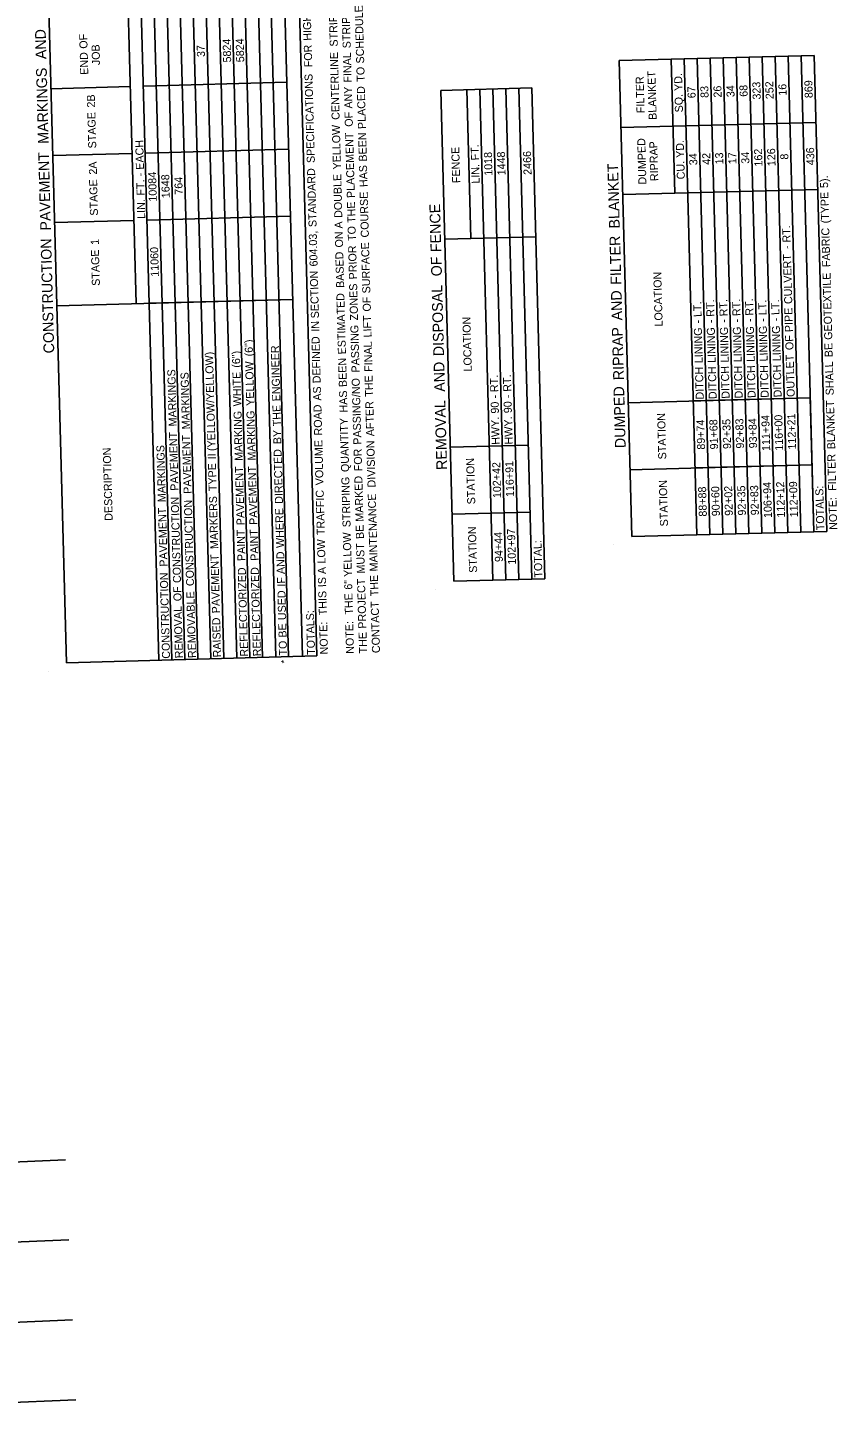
# Model space of a CAD drawing. Extents: x 1930091 to 1931962, y 596452 to 607874.
# Drawn here: x 1930751 to 1931358, y 596452 to 597489 of the extents above; entities that cross this region are included whole.
import ezdxf

# ---------------------------------------------------------------- set-up
doc = ezdxf.new("R2010")
doc.units = 0
for name, color, linetype in [('BR_Pr_Bent_CL', 7, 'Continuous'), ('Default', 7, 'Continuous'), ('R_Border', 7, 'Continuous')]:
    doc.layers.add(name, color=color, linetype=linetype)

msp = doc.modelspace()

# ---------------------------------------------------------------- linework, layer by layer
at = {"layer": 'BR_Pr_Bent_CL'}
for p, q in [((1930779.3, 596640.3), (1930579.5, 596631.6)), ((1930781.9, 596580.4), (1930582.1, 596571.7)), ((1930784.5, 596520.4), (1930584.7, 596511.8)), ((1930787.1, 596460.5), (1930587.3, 596451.8))]:
    msp.add_line(p, q, dxfattribs=at)
at = {"layer": 'Default'}
for p, q in [((1930832.2, 597282.1), (1930815, 597924.9)), ((1930849.2, 597014.8), (1930824.7, 597925.1)), ((1930858.9, 597015.1), (1930834.5, 597925.4)), ((1930868.7, 597015.3), (1930844.2, 597925.6)), ((1930878.4, 597015.6), (1930854, 597925.9)), ((1930888.2, 597015.8), (1930863.7, 597926.2)), ((1930897.9, 597016.1), (1930873.5, 597926.4)), ((1930907.7, 597016.4), (1930883.2, 597926.7)), ((1930917.4, 597016.6), (1930893, 597926.9)), ((1930927.1, 597016.9), (1930902.7, 597927.2)), ((1930936.9, 597017.1), (1930912.5, 597927.5)), ((1930946.6, 597017.4), (1930922.2, 597927.7)), ((1930956.9, 597017.7), (1930932.4, 597928)), ((1930967.6, 597018), (1930943.2, 597928.3)), ((1930780, 597012.9), (1930755.5, 597923.3)), ((1931340.5, 597468.1), (1931194.3, 597464.2)), ((1931311.1, 597110.3), (1931301.5, 597467.1)), ((1931320.8, 597110.6), (1931311.3, 597467.3)), ((1931330.6, 597110.9), (1931321, 597467.6)), ((1931340.3, 597111.1), (1931330.7, 597467.8)), ((1931350.1, 597111.4), (1931340.5, 597468.1)), ((1931203.9, 597107.5), (1931194.3, 597464.2)), ((1931236, 597364.8), (1931233.3, 597465.2)), ((1931252.6, 597108.8), (1931243, 597465.5)), ((1931262.4, 597109), (1931252.8, 597465.7)), ((1931272.1, 597109.3), (1931262.5, 597466)), ((1931281.8, 597109.5), (1931272.3, 597466.3)), ((1931291.6, 597109.8), (1931282, 597466.5)), ((1931301.3, 597110.1), (1931291.8, 597466.8)), ((1930945.3, 597448), (1930837.6, 597445.1)), ((1930945.3, 597448), (1930837.6, 597445.1)), ((1930827.9, 597444.8), (1930768.4, 597443.2)), ((1931128.8, 597443.8), (1931060.6, 597441.9)), ((1931128.8, 597443.8), (1931060.6, 597441.9)), ((1931070.5, 597074), (1931060.6, 597441.9)), ((1931083.1, 597330.9), (1931080.1, 597442.5)), ((1931099.7, 597074.8), (1931089.8, 597442.7)), ((1931109.4, 597075), (1931099.6, 597443)), ((1931119.2, 597075.3), (1931109.3, 597443.2)), ((1931128.9, 597075.6), (1931119.1, 597443.5)), ((1931138.7, 597075.8), (1931128.8, 597443.8)), ((1931341.8, 597417.9), (1931195.6, 597414)), ((1930829.2, 597394.6), (1930769.8, 597393)), ((1930946.7, 597397.8), (1930839, 597394.9)), ((1930946.7, 597397.8), (1930839, 597394.9)), ((1931343.2, 597367.7), (1931197, 597363.8)), ((1931343.2, 597367.7), (1931245.7, 597365.1)), ((1930830.6, 597344.5), (1930771.1, 597342.9)), ((1930948, 597347.6), (1930840.3, 597344.7)), ((1930948, 597347.6), (1930840.3, 597344.7)), ((1931131.8, 597332.2), (1931063.6, 597330.3)), ((1931131.8, 597332.2), (1931092.8, 597331.1)), ((1930949.7, 597285.2), (1930772.8, 597280.5)), ((1930949.7, 597285.2), (1930842, 597282.3)), ((1931337.6, 597211.5), (1931201.2, 597207.8)), ((1931337.6, 597211.5), (1931249.9, 597209.1)), ((1931340.3, 597111.1), (1931337.6, 597211.5)), ((1931126.2, 597176), (1931067.8, 597174.4)), ((1931126.2, 597176), (1931097, 597175.2)), ((1931339, 597161.3), (1931202.5, 597157.6)), ((1931339, 597161.3), (1931251.3, 597159)), ((1931127.6, 597125.8), (1931069.1, 597124.2)), ((1931127.6, 597125.8), (1931098.3, 597125)), ((1931350.1, 597111.4), (1931203.9, 597107.5)), ((1931350.1, 597111.4), (1931203.9, 597107.5)), ((1931138.7, 597075.8), (1931070.5, 597074)), ((1931138.7, 597075.8), (1931070.5, 597074)), ((1930967.6, 597018), (1930780, 597012.9)), ((1930967.6, 597018), (1930780, 597012.9))]:
    msp.add_line(p, q, dxfattribs=at)
at = {"layer": 'R_Border'}
for p, q in [((1931190.4, 597101.2), (1931190.4, 597101.2)), ((1931057, 597067.8), (1931057, 597067.8)), ((1930766.5, 597006.7), (1930766.5, 597006.7))]:
    msp.add_line(p, q, dxfattribs=at)

# ---------------------------------------------------------------- texts
at = {"layer": 'Default'}
for s, height, p in [(' HIGHWAY', 6, (1930963.8, 597477)), (' STRIPING.', 6, (1930993.2, 597471.3)), (' STRIPE', 6, (1930983.5, 597472.6)), (' SCHEDULE', 6, (1931003.3, 597459.9)), (' AND', 8, (1930765.1, 597462.4)), (' OF', 6, (1930795.9, 597471)), ('5824', 6, (1930903.5, 597462.9)), ('5824', 6, (1930913.3, 597463.1)), ('END', 6, (1930796.4, 597453.7)), ('JOB', 6, (1930805.2, 597460.9)), ('37', 6, (1930883.9, 597467)), (' FOR', 6, (1930964.4, 597457.1)), (' CENTERLINE', 6, (1930984.9, 597417.7)), (' FINAL', 6, (1930993.9, 597445.6)), (' MARKINGS', 8, (1930766.8, 597399)), (' TO', 6, (1931003.7, 597446.3)), (' SPECIFICATIONS', 6, (1930966.3, 597385.3)), ('FILTER', 6, (1931213.4, 597424.9)), ('BLANKET', 6, (1931222.5, 597419.9)), (' YD.', 6, (1931241.9, 597439.4)), ('323', 6, (1931300.5, 597435.1)), ('252', 6, (1931310.2, 597435.4)), ('16', 6, (1931319.9, 597438)), ('869', 6, (1931339.5, 597436.2)), (' 2B', 6, (1930801.6, 597426.9)), (' ANY', 6, (1930994.5, 597426.1)), (' PLACED', 6, (1931004.6, 597410.8)), ('SQ.', 6, (1931242.2, 597425.5)), ('67', 6, (1931251.7, 597436.1)), ('83', 6, (1931261.4, 597436.4)), ('26', 6, (1931271.2, 597436.6)), ('34', 6, (1931280.9, 597436.9)), ('68', 6, (1931290.7, 597437.2)), ('STAGE', 6, (1930802.4, 597398.5)), (' YELLOW', 6, (1930985.9, 597380.5)), (' OF', 6, (1930994.8, 597412.5)), (' PLACEMENT', 6, (1930996.3, 597359.1)), (' BEEN', 6, (1931005.3, 597386.4)), ('DUMPED', 6, (1931214.8, 597371.4)), (' PAVEMENT', 8, (1930768.5, 597334)), (' EACH', 6, (1930838.2, 597380.3)), ('FENCE', 6, (1931075.2, 597372.5)), (' FT.', 6, (1931089.4, 597387.3)), ('1018', 6, (1931099.4, 597378)), ('1448', 6, (1931109.2, 597378.3)), ('2466', 6, (1931128.7, 597378.7)), ('RIPRAP', 6, (1931223.7, 597374)), (' YD.', 6, (1931243.2, 597389.2)), ('34', 6, (1931253, 597385.9)), ('42', 6, (1931262.8, 597386.2)), ('13', 6, (1931272.5, 597386.5)), ('17', 6, (1931282.3, 597386.7)), ('34', 6, (1931292, 597387)), ('162', 6, (1931301.8, 597384.9)), ('126', 6, (1931311.6, 597385.2)), ('436', 6, (1931340.8, 597385.9)), (' 2A', 6, (1930803, 597376.6)), (' HAS', 6, (1931005.8, 597367.3)), ('LIN.', 6, (1931089.8, 597372.1)), (' BLANKET', 8, (1931194.9, 597335.5)), ('CU.', 6, (1931243.6, 597375.3)), ('8', 6, (1931321.2, 597390.1)), ('STAGE', 6, (1930803.7, 597348.1)), (' FT.', 6, (1930838.7, 597360.9)), (' -', 6, (1930838.3, 597375.2)), ('10084', 6, (1930847.8, 597358.6)), ('1648', 6, (1930857.5, 597361.2)), ('764', 6, (1930867.2, 597363.8)), (' STANDARD', 6, (1930967.6, 597337.3)), (' DOUBLE', 6, (1930986.9, 597344.2)), (' 5).', 6, (1931351.1, 597366.6)), (' COURSE', 6, (1931006.8, 597329.5)), (' (TYPE', 6, (1931351.8, 597340.1)), ('LIN.', 6, (1930839.1, 597345.7)), (' THE', 6, (1930996.8, 597340.4)), (' FENCE', 8, (1931061.1, 597317.8)), (' A', 6, (1930987.1, 597336.2)), (' 604.03,', 6, (1930968.4, 597307.8)), (' ON', 6, (1930987.5, 597322)), (' TO', 6, (1930997.1, 597326.9)), (' FILTER', 8, (1931196.1, 597293.3)), (' RT.', 6, (1931322.9, 597325.7)), (' FABRIC', 6, (1931352.7, 597307.3)), ('CONSTRUCTION', 8, (1930770.9, 597244.9)), (' 1', 6, (1930804.4, 597324)), ('STAGE', 6, (1930805.1, 597295.5)), ('11060', 6, (1930849.3, 597302.3)), (' PRIOR', 6, (1930997.9, 597298.1)), (' SURFACE', 6, (1931007.9, 597287.6)), (' -', 6, (1931323.1, 597320.9)), (' BASED', 6, (1930988.3, 597291.7)), (' OF', 8, (1931061.6, 597299.7)), (' CULVERT', 6, (1931324.2, 597279.6)), (' SECTION', 6, (1930969.4, 597268.9)), ('LOCATION', 6, (1931227, 597265)), (' GEOTEXTILE', 6, (1931354.2, 597252.8)), (' ZONES', 6, (1930998.7, 597267.3)), (' DISPOSAL', 8, (1931063.2, 597239.8)), (' AND', 8, (1931196.8, 597266.6)), (' ESTIMATED', 6, (1930989.6, 597241.9)), (' OF', 6, (1931008.3, 597274)), (' LT.', 6, (1931256.2, 597269.9)), (' RT.', 6, (1931265.9, 597270.1)), (' RT.', 6, (1931275.7, 597270.4)), (' RT.', 6, (1931285.4, 597270.6)), (' RT.', 6, (1931295.1, 597270.9)), (' LT.', 6, (1931304.9, 597271.2)), (' LT.', 6, (1931314.6, 597271.4)), (' LIFT', 6, (1931008.8, 597254.6)), ('LOCATION', 6, (1931083.9, 597231.3)), (' -', 6, (1931275.8, 597265.5)), (' -', 6, (1931285.5, 597265.8)), (' -', 6, (1931295.3, 597266)), (' -', 6, (1931305, 597266.3)), (' -', 6, (1931314.8, 597266.6)), (' PIPE', 6, (1931324.7, 597258.6)), (' IN', 6, (1930969.7, 597258.9)), (' PASSING', 6, (1930999.8, 597228.3)), (' RIPRAP', 8, (1931198, 597221.8)), (' LINING', 6, (1931257.1, 597235.3)), (' -', 6, (1931256.3, 597265)), (' LINING', 6, (1931266.8, 597235.5)), (' -', 6, (1931266, 597265.3)), (' LINING', 6, (1931276.6, 597235.8)), (' LINING', 6, (1931286.3, 597236)), (' LINING', 6, (1931296.1, 597236.3)), (' LINING', 6, (1931305.8, 597236.6)), (' LINING', 6, (1931315.6, 597236.8)), (' (6")', 6, (1930919.9, 597240.4)), (' ENGINEER', 6, (1930940.4, 597206.7)), (' DEFINED', 6, (1930970.7, 597220.2)), (' FINAL', 6, (1931009.5, 597228.8)), (' OF', 6, (1931325.1, 597245.1)), (' BE', 6, (1931354.5, 597239.8)), (' (YELLOW/YELLOW)', 6, (1930891.9, 597169.4)), (' (6")', 6, (1930910.4, 597231.9)), (' BEEN', 6, (1930990.3, 597217.4)), ('OUTLET', 6, (1931326, 597212.2)), (' MARKINGS', 6, (1930862.8, 597187.9)), (' MARKINGS', 6, (1930872.7, 597185.7)), (' WHITE', 6, (1930911.2, 597203)), (' YELLOW', 6, (1930920.9, 597203.3)), (' AND', 8, (1931063.9, 597213.1)), ('DITCH', 6, (1931257.8, 597210.3)), ('DITCH', 6, (1931267.5, 597210.6)), ('DITCH', 6, (1931277.2, 597210.9)), ('DITCH', 6, (1931287, 597211.1)), ('DITCH', 6, (1931296.7, 597211.4)), ('DITCH', 6, (1931306.5, 597211.6)), ('DITCH', 6, (1931316.2, 597211.9)), (' SHALL', 6, (1931355.3, 597211.2)), (' AS', 6, (1930971.1, 597207.2)), (' PASSING/NO', 6, (1931001.2, 597174.2)), (' THE', 6, (1931010, 597210.2)), (' RT.', 6, (1931103.8, 597213.6)), (' RT.', 6, (1931113.6, 597213.9)), ('DUMPED', 8, (1931199.3, 597173.9)), (' HAS', 6, (1930990.8, 597198.3)), (' AFTER', 6, (1931010.8, 597180.5)), ('REMOVAL', 8, (1931065.4, 597157.5)), (' 90', 6, (1931104.3, 597197.5)), (' -', 6, (1931104, 597208.8)), (' 90', 6, (1931114, 597197.8)), (' -', 6, (1931113.7, 597209)), (' BLANKET', 6, (1931356.4, 597170.8)), (' MARKING', 6, (1930912.3, 597162.1)), (' MARKING', 6, (1930922, 597162.3)), (' THE', 6, (1930940.9, 597188)), (' ROAD', 6, (1930971.8, 597181.1)), ('STATION', 6, (1931229.7, 597165.4)), ('111+94', 6, (1931307.6, 597171.7)), ('116+00', 6, (1931317.3, 597171.9)), ('112+21', 6, (1931327, 597172.8)), (' BY', 6, (1930941.2, 597174.6)), (' QUANTITY', 6, (1930992, 597153.7)), ('HWY.', 6, (1931104.8, 597176.4)), ('HWY.', 6, (1931114.6, 597176.6)), ('89+74', 6, (1931258.8, 597172.7)), ('91+68', 6, (1931268.5, 597172.9)), ('92+35', 6, (1931278.3, 597173.2)), ('92+83', 6, (1931288, 597173.5)), ('93+84', 6, (1931297.8, 597173.7)), (' PAVEMENT', 6, (1930864.1, 597139.7)), (' PAVEMENT', 6, (1930873.9, 597137.4)), (' VOLUME', 6, (1930972.8, 597143.8)), (' DIVISION', 6, (1931011.8, 597142.1)), ('DESCRIPTION', 6, (1930814.7, 597119.4)), (' MARKINGS', 6, (1930854.6, 597131.1)), (' II', 6, (1930892.1, 597163.2)), (' DIRECTED', 6, (1930942.4, 597129.9)), (' FOR', 6, (1931001.8, 597154.3)), ('  FILTER', 6, (1931357.2, 597137.4)), (' TYPE', 6, (1930892.7, 597139.4)), (' PAVEMENT', 6, (1930913.6, 597113.8)), (' PAVEMENT', 6, (1930923.3, 597114.1)), ('STATION', 6, (1931086.5, 597131.7)), ('102+42', 6, (1931105.9, 597136.4)), ('116+91', 6, (1931115.6, 597137.2)), (' STRIPING', 6, (1930993.1, 597112.3)), (' MARKED', 6, (1931002.8, 597116.5)), ('STATION', 6, (1931231, 597115.2)), ('92+83', 6, (1931299.1, 597123.5)), ('106+94', 6, (1931308.9, 597121.5)), ('112+12', 6, (1931318.7, 597121.8)), ('112+09', 6, (1931328.4, 597122)), (' CONSTRUCTION', 6, (1930866, 597070.5)), (' MARKERS', 6, (1930893.9, 597096)), (' TRAFFIC', 6, (1930973.8, 597106.4)), (' MAINTENANCE', 6, (1931013.5, 597079.2)), ('88+88', 6, (1931260.1, 597122.5)), ('90+60', 6, (1931269.9, 597122.8)), ('92+02', 6, (1931279.6, 597123.1)), ('92+35', 6, (1931289.4, 597123.3)), ('TOTALS:', 6, (1931348.2, 597112.3)), ('NOTE:', 6, (1931357.9, 597112.6)), (' PAVEMENT', 6, (1930855.9, 597082.8)), (' CONSTRUCTION', 6, (1930875.8, 597068.2)), (' WHERE', 6, (1930943.3, 597096.8)), (' BE', 6, (1931003.1, 597103.5)), ('STATION', 6, (1931087.9, 597080.4)), (' PAINT', 6, (1930914.3, 597087)), (' PAINT', 6, (1930924.1, 597087.2)), (' LOW', 6, (1930974.3, 597085.1)), (' YELLOW', 6, (1930994.1, 597075.1)), ('94+44', 6, (1931107.2, 597088.5)), ('102+97', 6, (1931117, 597086.5)), ('TOTAL:', 6, (1931136.8, 597076.8)), (' PAVEMENT', 6, (1930895.2, 597047.8)), (' AND', 6, (1930943.8, 597077.2)), (' MUST', 6, (1931003.8, 597077.6)), ('REFLECTORIZED', 6, (1930916.2, 597017.6)), ('REFLECTORIZED', 6, (1930925.9, 597017.8)), (' A', 6, (1930974.6, 597077.2)), ('CONSTRUCTION', 6, (1930857.7, 597016)), (' IF', 6, (1930944.1, 597067.8)), (' IS', 6, (1930974.8, 597067.4)), (' 6"', 6, (1930994.4, 597065.5)), (' PROJECT', 6, (1931004.9, 597036.3)), (' THE', 6, (1931014, 597060.6)), (' OF', 6, (1930866.4, 597056.9)), ('REMOVABLE', 6, (1930877.2, 597016.5)), (' USED', 6, (1930944.8, 597042.7)), ('  THIS', 6, (1930975.4, 597044.1)), ('  THE', 6, (1930994.9, 597044.6)), ('REMOVAL', 6, (1930867.4, 597016.3)), ('CONTACT', 6, (1931015.1, 597020.2)), ('RAISED', 6, (1930896, 597017)), (' BE', 6, (1930945.1, 597029.6)), ('TOTALS:', 6, (1930966.4, 597018.9)), ('NOTE:', 6, (1930976.1, 597019.2)), ('NOTE:', 6, (1930995.6, 597019.7)), ('THE', 6, (1931005.4, 597020)), ('TO', 6, (1930945.4, 597018.4)), ('*', 5, (1930945.8, 597012.5))]:
    msp.add_text(s, height=height, rotation=91.5377, dxfattribs=at).set_placement(p)

doc.saveas('drawing.dxf')
